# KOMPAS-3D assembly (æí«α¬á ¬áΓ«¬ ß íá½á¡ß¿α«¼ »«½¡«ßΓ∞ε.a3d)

Referenced files in D:\МОДЕЛЬ ТАНКА Т90\СБОРКИ\СБОРКА ХОДОВАЯ\: Сборка каток опорный.a3d, Сборка балансир с осями.a3d
Referenced files in D:\МОДЕЛЬ ТАНКА Т90\ДЕТАЛИ\ХОДОВАЯ\Каток опорный с балансиром\: крышка оси катка наружняя.m3d, крышка оси катка внутренняя.m3d
Referenced files in D:\МОДЕЛЬ ТАНКА Т90\ДЕТАЛИ\ОБЩИЕ ДЕТАЛИ\: гайка на 5.m3d, подшипник 8-4-2мм.m3d, гайка на 4.m3d
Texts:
  Сборка каток опорный с балансиром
